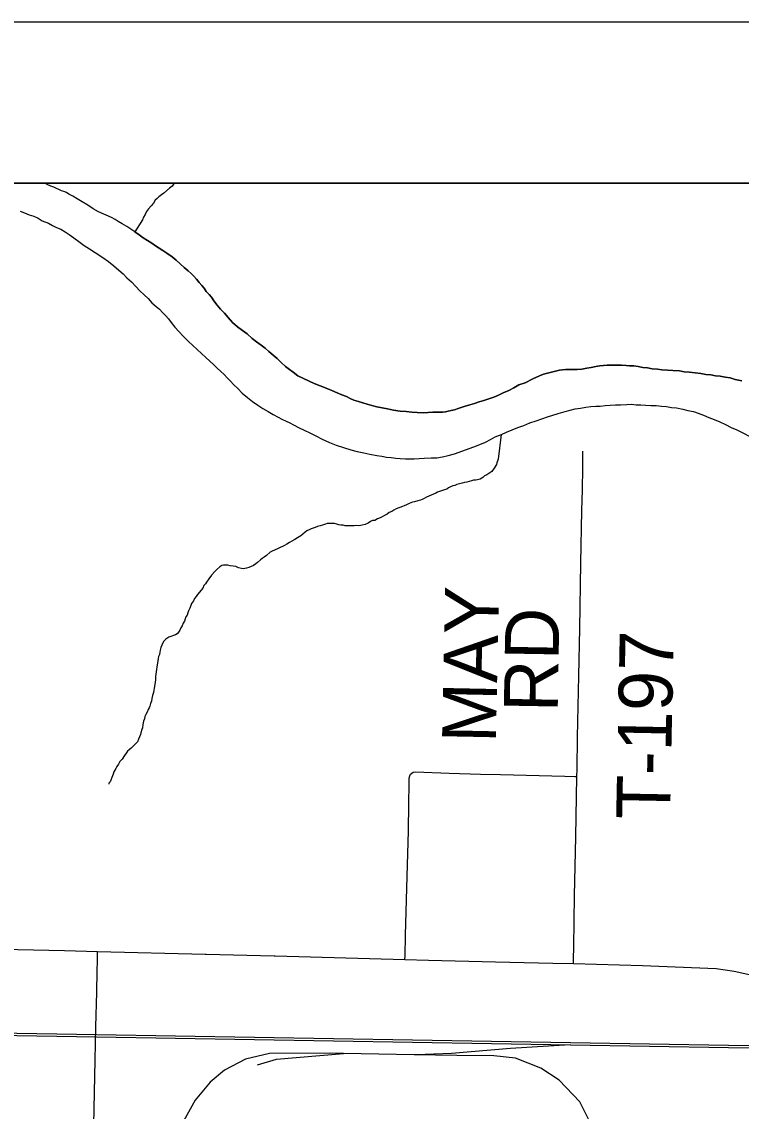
# Model space of a CAD drawing. Extents: x -483 to 680, y 0 to 440.
# Drawn here: x 124.7 to 162.6, y 347.1 to 404.4 of the extents above; entities that cross this region are included whole.
import ezdxf

# ---------------------------------------------------------------- set-up
doc = ezdxf.new("R2010")
doc.units = 0
for name, color, linetype in [('GM_X_County_Road', 7, 'Continuous'), ('GM_X_Major_River', 7, 'Continuous'), ('GM_X_Minor_River', 7, 'Continuous'), ('GM_X_Rail_Line', 7, 'Continuous'), ('GM_X_Township_Road', 7, 'Continuous'), ('GM_X_Township_Road_Text', 7, 'Continuous'), ('SH_Cut_Line', 7, 'Continuous'), ('SH_Text', 7, 'Continuous')]:
    doc.layers.add(name, color=color, linetype=linetype)

msp = doc.modelspace()

# ---------------------------------------------------------------- linework, layer by layer
at = {"layer": 'GM_X_County_Road'}
msp.add_line((134.372, 355.343), (137.957, 355.251), dxfattribs=at)
for points in [[(78.108, 356.589), (78.894, 356.586), (80.945, 356.555), (88.247, 356.38), (92.846, 356.286), (97.258, 356.171), (101.546, 356.078), (106.332, 355.972), (111.583, 355.872), (115.933, 355.76), (122.801, 355.615), (126.903, 355.532), (128.649, 355.488)], [(128.417, 344.657), (128.523, 349.753), (128.556, 351.507), (128.606, 353.34), (128.632, 354.456), (128.641, 355.012), (128.649, 355.488)], [(128.649, 355.488), (134.322, 355.345), (134.372, 355.343)], [(137.957, 355.251), (138.007, 355.25), (144.849, 355.06)], [(144.849, 355.06), (146.089, 355.025), (149.625, 354.945), (152.64, 354.877), (153.725, 354.847)], [(153.725, 354.847), (157.364, 354.75), (161.257, 354.596)], [(161.257, 354.596), (162.203, 354.455), (162.928, 354.294), (163.652, 354.153), (166.169, 353.509)]]:
    msp.add_lwpolyline(points, dxfattribs=at)
at = {"layer": 'GM_X_Major_River'}
for points in [[(130.62, 393.384), (130.396, 393.523), (130.19, 393.661), (129.947, 393.8), (129.742, 393.939), (129.573, 394.038), (129.386, 394.138), (128.69, 394.44), (128.409, 394.599), (128.13, 394.796), (127.83, 394.975), (127.568, 395.133), (127.344, 395.272), (127.137, 395.372), (127.006, 395.452), (126.875, 395.512), (126.743, 395.553), (126.612, 395.614), (126.48, 395.674), (126.349, 395.734), (126.179, 395.796), (125.991, 395.876), (125.865, 395.95)], [(124.57, 394.47), (124.795, 394.388), (125.04, 394.287), (125.285, 394.204), (125.51, 394.104), (125.735, 393.965), (126.054, 393.843), (126.279, 393.723), (126.486, 393.623), (126.711, 393.522), (126.936, 393.384), (127.16, 393.245), (127.402, 393.068), (127.663, 392.871), (127.943, 392.674), (128.224, 392.496), (128.523, 392.299), (128.934, 392.041), (129.233, 391.825), (129.512, 391.59), (129.772, 391.374), (129.995, 391.179), (130.199, 390.965), (130.44, 390.749), (130.662, 390.516), (130.884, 390.282)], [(124.57, 394.47), (124.795, 394.388), (125.04, 394.287), (125.285, 394.204), (125.51, 394.104), (125.735, 393.965), (126.054, 393.843), (126.279, 393.723), (126.486, 393.623), (126.711, 393.522), (126.936, 393.384), (127.16, 393.245), (127.402, 393.068), (127.663, 392.871), (127.943, 392.674), (128.224, 392.496), (128.523, 392.299), (128.934, 392.041), (129.233, 391.825), (129.512, 391.59), (129.772, 391.374), (129.995, 391.179), (130.199, 390.965), (130.44, 390.749), (130.662, 390.516), (130.884, 390.282)], [(155.115, 386.321), (154.906, 386.289), (154.657, 386.238), (154.429, 386.206), (154.18, 386.155), (153.933, 386.143), (153.61, 386.132), (153.306, 386.14), (153.002, 386.109), (152.16, 385.884), (151.949, 385.794), (151.585, 385.652), (151.181, 385.434), (150.855, 385.329), (150.585, 385.164), (150.316, 385.038), (150.028, 384.913), (149.778, 384.786), (149.528, 384.679), (149.279, 384.59), (149.011, 384.502), (148.762, 384.432), (148.513, 384.344), (148.265, 384.274), (147.977, 384.187), (147.652, 384.081), (147.46, 384.01), (147.288, 383.976), (147.136, 383.942), (146.983, 383.908), (146.831, 383.893), (146.679, 383.897), (146.526, 383.882), (146.318, 383.887), (146.07, 383.874), (145.842, 383.861), (145.5, 383.87), (145.216, 383.896), (144.913, 383.923), (144.591, 383.95), (144.25, 383.997), (143.929, 384.062), (143.645, 384.126), (143.362, 384.171), (143.097, 384.235), (142.853, 384.317), (142.626, 384.38), (142.4, 384.443), (142.155, 384.525), (141.967, 384.606), (141.761, 384.706), (141.516, 384.807), (141.272, 384.908), (140.99, 385.03), (140.689, 385.151), (140.388, 385.273), (140.069, 385.395), (139.205, 385.797), (138.963, 385.993), (138.758, 386.131), (138.552, 386.288), (138.33, 386.503), (138.107, 386.717), (137.903, 386.894), (137.68, 387.089), (137.475, 387.265), (137.27, 387.422), (137.028, 387.6), (136.804, 387.776), (136.525, 388.011), (136.283, 388.188), (136.022, 388.385), (135.762, 388.619), (135.54, 388.872), (135.337, 389.105), (135.134, 389.319), (134.949, 389.533), (134.784, 389.746), (134.655, 389.939), (134.526, 390.094), (134.378, 390.25), (134.269, 390.424), (134.139, 390.56), (134.01, 390.715), (133.863, 390.89), (133.715, 391.046), (133.586, 391.201), (133.418, 391.338), (133.213, 391.514), (133.009, 391.709), (132.786, 391.886), (132.581, 392.062), (132.301, 392.259), (132.096, 392.397), (131.89, 392.535), (131.704, 392.654), (131.517, 392.792), (131.274, 392.931), (131.049, 393.07), (130.844, 393.227), (130.62, 393.384)], [(130.62, 393.384), (130.844, 393.227), (131.049, 393.07), (131.274, 392.931), (131.517, 392.792), (131.704, 392.654), (131.89, 392.535), (132.096, 392.397), (132.301, 392.259), (132.581, 392.062), (132.786, 391.886), (133.009, 391.709), (133.213, 391.514), (133.418, 391.338), (133.586, 391.201), (133.715, 391.046), (133.863, 390.89), (134.01, 390.715), (134.139, 390.56), (134.269, 390.424), (134.378, 390.25), (134.526, 390.094), (134.655, 389.939), (134.784, 389.746), (134.949, 389.533), (135.134, 389.319), (135.337, 389.105), (135.54, 388.872), (135.762, 388.619), (136.022, 388.385), (136.283, 388.188), (136.525, 388.011), (136.804, 387.776), (137.028, 387.6), (137.27, 387.422), (137.475, 387.265), (137.68, 387.089), (137.903, 386.894), (138.107, 386.717), (138.33, 386.503), (138.552, 386.288), (138.758, 386.131), (138.963, 385.993), (139.205, 385.797), (140.069, 385.395), (140.388, 385.273), (140.689, 385.151), (140.99, 385.03), (141.272, 384.908), (141.516, 384.807), (141.761, 384.706), (141.967, 384.606), (142.155, 384.525), (142.4, 384.443), (142.626, 384.38), (142.853, 384.317), (143.097, 384.235), (143.362, 384.171), (143.645, 384.126), (143.929, 384.062), (144.25, 383.997), (144.591, 383.95), (144.913, 383.923), (145.216, 383.896), (145.5, 383.87), (145.842, 383.861), (146.07, 383.874), (146.318, 383.887), (146.526, 383.882), (146.679, 383.897), (146.831, 383.893), (146.983, 383.908), (147.136, 383.942), (147.288, 383.976), (147.46, 384.01), (147.652, 384.081), (147.977, 384.187), (148.265, 384.274), (148.513, 384.344), (148.762, 384.432), (149.011, 384.502), (149.279, 384.59), (149.528, 384.679), (149.778, 384.786), (150.028, 384.913), (150.316, 385.038), (150.585, 385.164), (150.855, 385.329), (151.181, 385.434), (151.585, 385.652), (151.949, 385.794), (152.16, 385.884), (153.002, 386.109), (153.306, 386.14), (153.61, 386.132), (153.933, 386.143), (154.18, 386.155), (154.429, 386.206), (154.657, 386.238), (154.906, 386.289), (155.115, 386.321)], [(130.884, 390.282), (131.107, 390.068), (131.311, 389.873), (131.514, 389.64), (131.738, 389.463), (131.905, 389.307), (132.071, 389.132), (132.238, 388.956), (132.386, 388.801), (132.533, 388.607), (132.717, 388.374), (132.939, 388.141), (133.161, 387.888), (133.439, 387.615), (134.348, 386.776), (134.571, 386.58), (134.775, 386.385), (134.961, 386.209), (135.128, 386.053), (135.313, 385.877), (135.48, 385.702), (135.647, 385.527), (135.813, 385.352), (136.036, 385.137), (136.276, 384.884), (136.556, 384.668), (136.816, 384.453), (137.096, 384.256), (137.358, 384.078), (137.638, 383.919), (137.9, 383.76), (138.163, 383.621), (138.369, 383.52), (138.595, 383.42), (138.782, 383.32), (138.969, 383.22), (139.269, 383.061), (139.532, 382.94), (139.833, 382.799), (140.152, 382.639), (140.489, 382.46), (140.865, 382.298), (141.222, 382.156), (141.618, 382.032), (141.995, 381.909), (142.334, 381.824), (142.674, 381.739), (142.995, 381.674), (143.374, 381.608), (143.638, 381.563), (143.884, 381.518), (144.13, 381.493), (144.377, 381.468), (144.604, 381.443), (144.87, 381.436), (145.117, 381.43), (145.344, 381.424), (145.592, 381.456), (145.858, 381.468), (146.238, 381.477), (146.523, 381.489), (146.829, 381.538), (147.134, 381.606), (147.459, 381.693), (148.475, 382.066), (148.801, 382.191), (149.089, 382.316), (149.358, 382.442), (149.609, 382.588), (149.935, 382.712), (150.204, 382.838), (150.492, 382.964), (150.799, 383.089), (151.124, 383.195), (151.431, 383.32), (151.757, 383.425), (152.064, 383.532), (152.37, 383.638), (152.638, 383.726), (152.925, 383.813), (153.289, 383.918), (153.556, 383.987), (153.824, 384.056), (154.11, 384.106), (154.377, 384.156), (154.644, 384.187), (154.91, 384.2), (155.138, 384.213), (155.405, 384.244), (155.671, 384.256), (155.938, 384.268), (156.204, 384.281), (156.546, 384.291), (156.793, 384.304), (157.039, 384.278), (157.286, 384.272), (157.533, 384.266), (157.817, 384.239), (158.083, 384.233), (158.367, 384.206), (158.632, 384.181)], [(130.884, 390.282), (131.107, 390.068), (131.311, 389.873), (131.514, 389.64), (131.738, 389.463), (131.905, 389.307), (132.071, 389.132), (132.238, 388.956), (132.386, 388.801), (132.533, 388.607), (132.717, 388.374), (132.939, 388.141), (133.161, 387.888), (133.439, 387.615), (134.348, 386.776), (134.571, 386.58), (134.775, 386.385), (134.961, 386.209), (135.128, 386.053), (135.313, 385.877), (135.48, 385.702), (135.647, 385.527), (135.813, 385.352), (136.036, 385.137), (136.276, 384.884), (136.556, 384.668), (136.816, 384.453), (137.096, 384.256), (137.358, 384.078), (137.638, 383.919), (137.9, 383.76), (138.163, 383.621), (138.369, 383.52), (138.595, 383.42), (138.782, 383.32), (138.969, 383.22), (139.269, 383.061), (139.532, 382.94), (139.833, 382.799), (140.152, 382.639), (140.489, 382.46), (140.865, 382.298), (141.222, 382.156), (141.618, 382.032), (141.995, 381.909), (142.334, 381.824), (142.674, 381.739), (142.995, 381.674), (143.374, 381.608), (143.638, 381.563), (143.884, 381.518), (144.13, 381.493), (144.377, 381.468), (144.604, 381.443), (144.87, 381.436), (145.117, 381.43), (145.344, 381.424), (145.592, 381.456), (145.858, 381.468), (146.238, 381.477), (146.523, 381.489), (146.829, 381.538), (147.134, 381.606), (147.459, 381.693), (148.475, 382.066), (148.801, 382.191), (149.089, 382.316), (149.358, 382.442), (149.609, 382.588), (149.935, 382.712), (150.204, 382.838), (150.492, 382.964), (150.799, 383.089), (151.124, 383.195), (151.431, 383.32), (151.757, 383.425), (152.064, 383.532), (152.37, 383.638), (152.638, 383.726), (152.925, 383.813), (153.289, 383.918), (153.556, 383.987), (153.824, 384.056), (154.11, 384.106), (154.377, 384.156), (154.644, 384.187), (154.91, 384.2), (155.138, 384.213), (155.405, 384.244), (155.671, 384.256), (155.938, 384.268), (156.204, 384.281), (156.546, 384.291), (156.793, 384.304), (157.039, 384.278), (157.286, 384.272), (157.533, 384.266), (157.817, 384.239), (158.083, 384.233), (158.367, 384.206), (158.632, 384.181)], [(162.598, 385.542), (162.258, 385.608), (161.994, 385.69), (161.729, 385.735), (161.464, 385.78), (161.218, 385.805), (160.972, 385.849), (160.707, 385.875), (160.442, 385.92), (160.14, 385.965), (159.855, 385.992), (159.571, 386.018), (159.325, 386.062), (158.965, 386.09), (158.68, 386.098), (158.396, 386.124), (158.169, 386.149), (157.885, 386.175), (157.639, 386.219), (157.393, 386.244), (157.147, 386.289), (156.92, 386.332), (156.692, 386.338), (156.502, 386.343), (156.256, 386.368), (156.085, 386.373), (155.876, 386.359), (155.686, 386.364), (155.515, 386.368), (155.306, 386.354), (155.115, 386.321)], [(155.115, 386.321), (155.306, 386.354), (155.515, 386.368), (155.686, 386.364), (155.876, 386.359), (156.085, 386.373), (156.256, 386.368), (156.502, 386.343), (156.692, 386.338), (156.92, 386.332), (157.147, 386.289), (157.393, 386.244), (157.639, 386.219), (157.885, 386.175), (158.169, 386.149), (158.396, 386.124), (158.68, 386.098), (158.965, 386.09), (159.325, 386.062), (159.571, 386.018), (159.855, 385.992), (160.14, 385.965), (160.442, 385.92), (160.707, 385.875), (160.972, 385.849), (161.218, 385.805), (161.464, 385.78), (161.729, 385.735), (161.994, 385.69), (162.258, 385.608), (162.598, 385.542)], [(158.632, 384.181), (158.897, 384.136), (159.162, 384.11), (159.503, 384.045), (159.767, 383.981), (160.05, 383.917), (160.295, 383.835), (160.577, 383.732), (160.859, 383.611), (161.142, 383.509), (161.442, 383.387), (161.743, 383.247), (162.043, 383.087), (162.343, 382.966), (163.337, 382.447)], [(158.632, 384.181), (158.897, 384.136), (159.162, 384.11), (159.503, 384.045), (159.767, 383.981), (160.05, 383.917), (160.295, 383.835), (160.577, 383.732), (160.859, 383.611), (161.142, 383.509), (161.442, 383.387), (161.743, 383.247), (162.043, 383.087), (162.343, 382.966), (163.337, 382.447)]]:
    msp.add_lwpolyline(points, dxfattribs=at)
at = {"layer": 'GM_X_Minor_River'}
for points in [[(132.689, 395.95), (132.58, 395.784), (132.444, 395.692), (132.134, 395.416), (132.018, 395.343), (131.882, 395.232), (131.785, 395.14), (131.688, 395.047), (131.589, 394.898), (131.471, 394.749), (131.334, 394.6), (131.236, 394.451), (131.156, 394.301), (131.076, 394.151), (131.016, 394.02), (130.62, 393.384)], [(149.927, 382.709), (149.769, 381.406), (149.688, 381.218), (149.667, 381.124), (149.548, 380.937), (149.43, 380.769), (149.315, 380.696), (149.16, 380.586), (149.044, 380.532), (148.947, 380.44), (148.812, 380.367), (148.679, 380.333), (148.583, 380.316), (148.469, 380.3), (148.354, 380.265), (148.239, 380.23), (148.105, 380.195), (147.991, 380.179), (147.857, 380.145), (147.723, 380.11), (147.59, 380.076), (147.474, 380.021), (147.379, 380.005), (147.245, 379.951), (147.148, 379.897), (147.052, 379.842), (146.937, 379.807), (146.822, 379.772), (146.669, 379.719), (146.573, 379.684), (146.477, 379.629), (146.361, 379.575), (146.227, 379.522), (146.112, 379.468), (145.978, 379.414), (145.862, 379.341), (145.765, 379.286), (145.67, 379.251), (145.536, 379.216), (145.345, 379.164), (145.249, 379.148), (145.076, 379.076), (144.923, 379.004), (144.807, 378.95), (144.712, 378.915), (144.386, 378.79), (144.27, 378.736), (144.154, 378.663), (144.02, 378.609), (143.904, 378.517), (143.769, 378.445), (143.653, 378.372), (143.538, 378.318), (143.404, 378.264), (143.269, 378.192), (143.136, 378.176), (143.039, 378.122), (142.904, 378.049), (142.751, 377.977), (142.598, 377.943), (142.503, 377.927), (142.388, 377.911), (142.293, 377.913), (142.179, 377.897), (142.084, 377.899), (141.97, 377.902), (141.818, 377.906), (141.704, 377.909), (141.591, 377.931), (141.477, 377.934), (141.364, 377.956), (141.251, 377.997), (141.137, 378.019), (141.024, 378.021), (140.929, 378.024), (140.758, 378.028), (140.662, 377.993), (140.509, 377.94), (140.375, 377.905), (140.241, 377.87), (140.126, 377.816), (140.011, 377.781), (139.915, 377.746), (139.8, 377.692), (139.684, 377.638), (139.588, 377.564), (139.471, 377.472), (139.355, 377.38), (139.181, 377.271), (139.046, 377.179), (138.892, 377.088), (138.757, 377.016), (138.622, 376.943), (138.507, 376.87), (138.161, 376.708), (137.968, 376.618), (137.853, 376.564), (137.738, 376.51), (137.544, 376.344), (137.427, 376.252)], [(137.427, 376.252), (137.331, 376.179), (137.234, 376.105), (137.079, 375.976), (136.982, 375.903), (136.866, 375.811), (136.75, 375.757), (136.616, 375.703), (136.501, 375.668), (136.329, 375.635), (136.235, 375.656), (136.084, 375.698), (135.934, 375.759), (135.801, 375.781), (135.631, 375.804), (135.517, 375.826), (135.404, 375.829), (135.29, 375.832), (135.194, 375.816), (135.098, 375.742), (134.942, 375.594), (134.826, 375.502), (134.65, 375.298), (134.512, 375.111), (134.394, 374.944), (134.334, 374.85), (134.256, 374.757), (134.196, 374.626), (133.922, 374.291), (133.843, 374.179), (133.764, 374.067), (133.704, 373.955), (133.606, 373.805), (133.565, 373.711), (133.505, 373.561), (133.444, 373.43), (133.403, 373.317), (133.363, 373.204), (133.303, 373.11), (133.262, 372.997), (133.222, 372.885), (133.162, 372.772), (133.102, 372.641), (133.042, 372.528), (132.982, 372.416), (132.922, 372.304), (132.844, 372.211), (132.748, 372.156), (132.652, 372.121), (132.556, 372.085), (132.403, 372.032), (132.248, 371.941), (132.131, 371.811), (132.032, 371.624), (131.99, 371.492), (131.949, 371.36), (131.927, 371.247), (131.905, 371.133), (131.865, 371.02), (131.843, 370.907), (131.821, 370.794), (131.799, 370.661), (131.775, 370.472), (131.752, 370.34), (131.73, 370.207), (131.727, 370.093), (131.705, 369.961), (131.701, 369.809), (131.679, 369.658), (131.633, 369.355), (131.611, 369.242), (131.589, 369.128), (131.547, 368.958), (131.505, 368.808), (131.483, 368.675), (131.442, 368.543), (131.4, 368.411), (131.36, 368.318), (131.32, 368.224), (131.259, 368.092), (131.199, 367.961), (131.14, 367.867), (131.117, 367.735), (131.077, 367.622), (131.055, 367.528), (131.034, 367.433), (131.011, 367.263), (130.989, 367.169), (130.928, 366.999), (130.907, 366.905), (130.866, 366.792), (130.806, 366.661), (130.745, 366.529), (130.648, 366.418), (130.511, 366.288), (130.414, 366.196), (130.317, 366.103), (130.22, 366.03), (130.161, 365.936), (130.063, 365.806), (129.944, 365.619)], [(129.944, 365.619), (129.827, 365.489), (129.747, 365.358), (129.668, 365.228), (129.608, 365.115), (129.509, 364.947), (129.468, 364.815), (129.407, 364.645), (129.346, 364.514), (129.306, 364.42), (129.247, 364.346), (129.246, 364.289)]]:
    msp.add_lwpolyline(points, dxfattribs=at)
at = {"layer": 'GM_X_Rail_Line'}
msp.add_line((145.329, 350.047), (141.617, 350.114), dxfattribs=at)
for points in [[(45.608, 365.186), (70.759, 356.775), (78.191, 354.285), (81.655, 353.305), (84.729, 352.716), (87.182, 352.258), (89.991, 351.898), (92.932, 351.702), (128.6, 351.112), (161.911, 350.555), (167.481, 350.522), (171.603, 350.391), (175.463, 350.653), (180.867, 350.948), (187.285, 351.472), (192.002, 351.898), (217.44, 353.96)], [(45.608, 365.055), (70.719, 356.657), (78.155, 354.167), (81.627, 353.184), (84.706, 352.594), (87.162, 352.135), (89.979, 351.774), (92.927, 351.578), (128.598, 350.988), (161.91, 350.431), (167.478, 350.398), (171.606, 350.267), (175.471, 350.529), (180.875, 350.824), (187.295, 351.348), (192.012, 351.774), (217.193, 353.826)], [(141.617, 350.114), (140.91, 350.127), (137.714, 350.107), (136.45, 349.809), (135.341, 349.233), (134.59, 348.596), (133.799, 347.661), (133.183, 346.551)], [(137.077, 349.511), (138.074, 349.819), (141.617, 350.114)], [(153.558, 350.57), (150.414, 350.374), (147.301, 350.107), (145.441, 350.045), (145.329, 350.047)], [(154.822, 346.048), (154.062, 347.558), (152.973, 348.709), (152.007, 349.336), (150.671, 349.86), (149.541, 349.993), (147.578, 350.004), (145.329, 350.047)]]:
    msp.add_lwpolyline(points, dxfattribs=at)
at = {"layer": 'GM_X_Township_Road'}
for points in [[(153.911, 364.699), (153.918, 365.095), (153.949, 366.774), (154.016, 370.007), (154.059, 372.494), (154.123, 375.944), (154.173, 378.711), (154.206, 379.798), (154.225, 380.961), (154.226, 381.843)], [(144.849, 355.06), (144.855, 355.261), (144.883, 356.349), (144.987, 360.044), (145.034, 361.814), (145.059, 363.274), (145.072, 364.3), (145.079, 364.611), (145.103, 364.732), (145.144, 364.815), (145.208, 364.882), (145.29, 364.923), (145.412, 364.943), (147.182, 364.875), (148.828, 364.827), (149.884, 364.809), (153.269, 364.716), (153.805, 364.702), (153.911, 364.699)], [(153.725, 354.847), (153.73, 355.07), (153.743, 355.743), (153.786, 358.412), (153.85, 361.52), (153.911, 364.699)]]:
    msp.add_lwpolyline(points, dxfattribs=at)
at = {"layer": 'SH_Cut_Line'}
msp.add_lwpolyline([(385.608, 55.95), (385.608, 395.95), (45.608, 395.95), (45.608, 281.486), (47.873, 281.454), (57.759, 281.293), (64.783, 281.226), (67.114, 281.188), (73.333, 281.086), (75.975, 281.043), (77.151, 281.034), (77.105, 279.466), (77.065, 275.738), (77.043, 273.874), (76.996, 269.37), (76.941, 265.642), (76.868, 261.138), (76.791, 256.013), (76.689, 249.801), (76.636, 246.539)], dxfattribs=at)
at = {"layer": 'SH_Text'}
for points in [[(37.108, 404.45), (394.108, 404.45), (394.108, 47.45), (37.108, 47.45)], [(45.608, 395.95), (385.608, 395.95), (385.608, 55.95), (45.608, 55.95)]]:
    msp.add_lwpolyline(points, close=True, dxfattribs=at)

# ---------------------------------------------------------------- texts
at = {"layer": 'GM_X_Township_Road_Text'}
for s, rotation, p in [('MAY', 88.81888, (149.641, 366.453)), ('RD', 89.00935, (152.899, 368.075)), ('T-197', 88.88396, (158.821, 362.421))]:
    msp.add_text(s, height=2.8409, rotation=rotation, dxfattribs=at).set_placement(p)

doc.saveas('drawing.dxf')
